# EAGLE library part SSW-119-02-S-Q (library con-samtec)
THROUGH-HOLE .025" SQ POST SOCKET Source: Samtec SSW.pdf
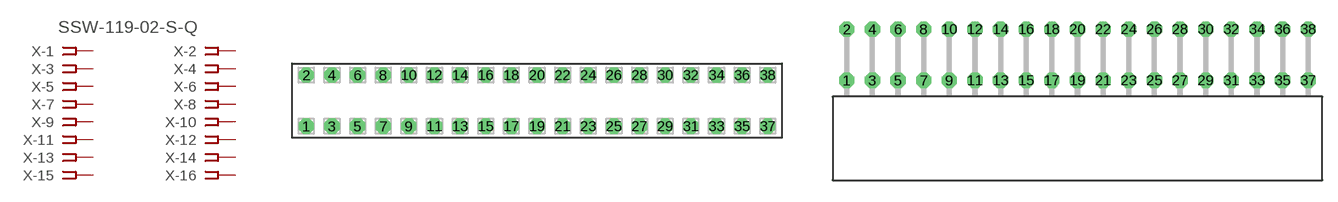
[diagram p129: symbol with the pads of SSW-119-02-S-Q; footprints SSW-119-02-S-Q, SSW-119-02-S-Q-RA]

Designator prefix X; gates -1=FPINV -2=FPIN -3=FPIN -4=FPIN -5=FPIN -6=FPIN -7=FPIN -8=FPIN -9=FPIN -10=FPIN -11=FPIN -12=FPIN -13=FPIN -14=FPIN -15=FPIN -16=FPIN -17=FPIN -18=FPIN -19=FPIN -20=FPIN -21=FPIN -22=FPIN -23=FPIN -24=FPIN -25=FPIN -26=FPIN -27=FPIN -28=FPIN -29=FPIN -30=FPIN -31=FPIN -32=FPIN -33=FPIN -34=FPIN -35=FPIN -36=FPIN -37=FPIN -38=FPIN

## SSW-119-02-S-Q (MPN: SSW-119-02-S-Q; OC_FARNELL: unknown; OC_NEWARK: 82P8016)  [SSW-119-02-S-Q]
1  -1:1  pas
2  -2:1  pas
3  -3:1  pas
4  -4:1  pas
5  -5:1  pas
6  -6:1  pas
7  -7:1  pas
8  -8:1  pas
9  -9:1  pas
10  -10:1  pas
11  -11:1  pas
12  -12:1  pas
13  -13:1  pas
14  -14:1  pas
15  -15:1  pas
16  -16:1  pas
17  -17:1  pas
18  -18:1  pas
19  -19:1  pas
20  -20:1  pas
21  -21:1  pas
22  -22:1  pas
23  -23:1  pas
24  -24:1  pas
25  -25:1  pas
26  -26:1  pas
27  -27:1  pas
28  -28:1  pas
29  -29:1  pas
30  -30:1  pas
31  -31:1  pas
32  -32:1  pas
33  -33:1  pas
34  -34:1  pas
35  -35:1  pas
36  -36:1  pas
37  -37:1  pas
38  -38:1  pas

## SSW-119-02-S-QRA (MPN: SSW-119-02-S-Q-RA; OC_FARNELL: unknown; OC_NEWARK: 82P8017)  [SSW-119-02-S-Q-RA]
Pads as for SSW-119-02-S-Q

## Footprint SSW-119-02-S-Q (pad centres in mm)
THROUGH-HOLE .025" SQ POST SOCKET Source: Samtec SSW.pdf
drill 1 pad 1.5 octagon: 1 -22.86,-2.54; 2 -22.86,2.54; 3 -20.32,-2.54; 4 -20.32,2.54; 5 -17.78,-2.54; 6 -17.78,2.54; 7 -15.24,-2.54; 8 -15.24,2.54; 9 -12.7,-2.54; 10 -12.7,2.54; 11 -10.16,-2.54; 12 -10.16,2.54; 13 -7.62,-2.54; 14 -7.62,2.54; 15 -5.08,-2.54; 16 -5.08,2.54; 17 -2.54,-2.54; 18 -2.54,2.54; 19 0,-2.54; 20 0,2.54; 21 2.54,-2.54; 22 2.54,2.54; 23 5.08,-2.54; 24 5.08,2.54; 25 7.62,-2.54; 26 7.62,2.54; 27 10.16,-2.54; 28 10.16,2.54; 29 12.7,-2.54; 30 12.7,2.54; 31 15.24,-2.54; 32 15.24,2.54; 33 17.78,-2.54; 34 17.78,2.54; 35 20.32,-2.54; 36 20.32,2.54; 37 22.86,-2.54; 38 22.86,2.54

## Footprint SSW-119-02-S-Q-RA (pad centres in mm)
THROUGH-HOLE .025" SQ POST SOCKET Source: Samtec SSW.pdf
drill 1 pad 1.5 octagon: 1 -22.86,1.524; 2 -22.86,6.604; 3 -20.32,1.524; 4 -20.32,6.604; 5 -17.78,1.524; 6 -17.78,6.604; 7 -15.24,1.524; 8 -15.24,6.604; 9 -12.7,1.524; 10 -12.7,6.604; 11 -10.16,1.524; 12 -10.16,6.604; 13 -7.62,1.524; 14 -7.62,6.604; 15 -5.08,1.524; 16 -5.08,6.604; 17 -2.54,1.524; 18 -2.54,6.604; 19 0,1.524; 20 0,6.604; 21 2.54,1.524; 22 2.54,6.604; 23 5.08,1.524; 24 5.08,6.604; 25 7.62,1.524; 26 7.62,6.604; 27 10.16,1.524; 28 10.16,6.604; 29 12.7,1.524; 30 12.7,6.604; 31 15.24,1.524; 32 15.24,6.604; 33 17.78,1.524; 34 17.78,6.604; 35 20.32,1.524; 36 20.32,6.604; 37 22.86,1.524; 38 22.86,6.604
